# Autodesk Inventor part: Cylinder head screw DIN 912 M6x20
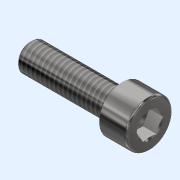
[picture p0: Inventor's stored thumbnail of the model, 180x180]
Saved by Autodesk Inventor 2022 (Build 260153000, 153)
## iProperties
Category: PARTsolutions
Company: METALWORK
Part Number: Cylinder head screw DIN 912 M6x20
Material: Generico
Catalog Web Link: www.cadenas.de
Description: DIN 912-Cylinder head screws cap screws
Vendor: METALWORK
Document SubType Name: Modeling
Designer: partserver
Manufacturer: METALWORK
Mass: 0.844568 g
Surface Area: 6.8049 cm^2
Volume: 0.844568 cm^3
Density: 1 g/cm^3
Appearance: Acciaio - Lucido
PSOL_IDENT_0: {$CADENAS_DATA\23d-libs\metalwork\commonpool\din_912.prj},208 {VTYP=3D},{NB=Cylinder head screw DIN
PSOL_IDENT_1: 912 M6x16},{LINA=Cylinder head screw DIN 912 M6x16},{NN=DIN 912},{DATE=09.11.2020 15:05:54},{GEOMDAT
PSOL_IDENT_2: E=27.11.2019 13:03:54},{VERSION=},{LINEID=690},{WBVAR=},{WBNUMERIC=}  {NB=Zylinderschraube DIN 912 M
PSOL_IDENT_3: 6x16},{LINA=Zylinderschraube DIN 912 M6x16},{KT=X},{IDNR=},{VER=x},{GEW=0},{D=6.000},{D3=4.773},{P=1
PSOL_IDENT_4: .000},{L=16.000},{B=13},{BX=24.000},{LS=0},{LG=3},{DK=10.000},{DA=6.800},{DS=6.000},{E=5.720},{F=0.6
PSOL_IDENT_5: 80},{K=6.000},{R=0.250},{S=5.000},{T=3.000},{V=0.600},{DW=9.380},{W=2.300},{NENN=M6x16}
NB: Cylinder head screw DIN 912 M6x16
NN: DIN 912
NT: Cylinder head screws cap screws
NBSYN: Cylinder head screw DIN 912 $NENN.
LINA: Cylinder head screw DIN 912 M6x16
CATALOG: Metalwork
VER: x
GEW: 0
D: 6
D3: 4.773
P: 1
L: 16
BX: 24
DK: 10
DA: 6.8
DS: 6
E: 5.72
F: 0.68
K: 6
R: 0.25
S: 5
T: 3
V: 0.6
DW: 9.38
W: 2.3
SUPPLIER: METALWORK
ARTICLENO: Cylinder head screw DIN 912 M6x16
BOMINFO: Cylinder head screw DIN 912 M6x16
CREATOR: CADENAS GmbH
Title: Cylinder head screw DIN 912 M6x16
Author: Cadenas PARTsolutions
Comments: Cylinder head screws cap screws
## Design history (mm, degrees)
sketch "Sketch_1"
  geometry: L1 (-16, 0)-(6, 0); L2 (3, 0)-(3, -2.5); L3 (3, -2.5)-(5.759, -2.5); L4 (5.759, -2.5)-(6, -2.917); L5 (6, -2.917)-(6, -4.4); L6 (5.4, -5)-(0, -5); L7 (0, -5)-(0, -3.4); L8 (-0.168, -3.164)-(-0.598, -3.014); L9 (-0.68, -3)-(-15.387, -3); L10 (-16, 0)-(3, 0); L11 (-16, 0)-(-20, 0); L12 (-20, 0)-(-20, -2.5); L13 (-19.5, -3)-(-16, -3); L14 (-16, -3)-(-15.387, -3); L15 (-19.5, -3)-(-20, -2.5); A1 r 0.6 centre (5.4, -4.4) between (5.4, -5) and (6, -4.4); A2 r 0.25 centre (-0.25, -3.4) between (0, -3.4) and (-0.168, -3.164); A3 r 0.25 centre (-0.68, -3.25) between (-0.598, -3.014) and (-0.68, -3); 1 further point
  constraints: 30 end point, 6 point on circle, 3 centre point, 2 horizontal, 2 point on line, 1 parallel, 1 perpendicular
  dimensions: "d10" = 3 distance between parallel lines of L1 L9; "d12" = 5.4 distance of L6.start L6.end; "d13" = 4 distance of L13.end point (-20, -3); "d14" = 0.5 distance of L13.start point (-20, -3); "d15" = 0.5 distance of L12.end point (-20, -3) (= d14)
revolve "Revolution1" sketch "Sketch_1" stored, may be unused: angle "d0" = 360 deg
thread "Thread1" dims "d1" = 18.82, "d2" = 0
sketch "Skizze_1"
  geometry: L1 (-2.5, -1.443)-(0, -2.887); L2 (0, -2.887)-(2.5, -1.443); L3 (2.5, -1.443)-(2.5, 1.443); L4 (2.5, 1.443)-(0, 2.887); L5 (0, 2.887)-(-2.5, 1.443); L6 (-2.5, 1.443)-(-2.5, -1.443)
  constraints: 12 end point
extrude "Extrusion1" cut sketch "Skizze_1" distance "d3" = 3; taper "d4" = 0 deg
sketch "Sketch_4"
  geometry: L1 (-1.557, 0)-(-3, 0); L2 (-3, 0)-(-3, 2.5); L3 (-3, 2.5)-(-1.557, 0); L4 (-1.557, 0)-(-3, 0)
  constraints: 8 end point
revolve "Revolution2" sketch "Sketch_4" stored, may be unused: angle "d5" = 360 deg
node "ip1_XY"
node "ip1_YZ"
node "ip1_ZX"
node "ip1_X"
node "ip1_Y"
node "ip1_Z"
node "ip1_Center"
node "ip2_XY"
node "ip2_YZ"
node "ip2_ZX"
node "ip2_X"
node "ip2_Y"
node "ip2_Z"
node "ip2_Center"
node "ip3_XY"
node "ip3_YZ"
node "ip3_ZX"
node "ip3_X"
node "ip3_Y"
node "ip3_Z"
node "ip3_Center"
body "Solid1"
other parameters: "d6" = 0, "d7" = 0, "d8" = 0
